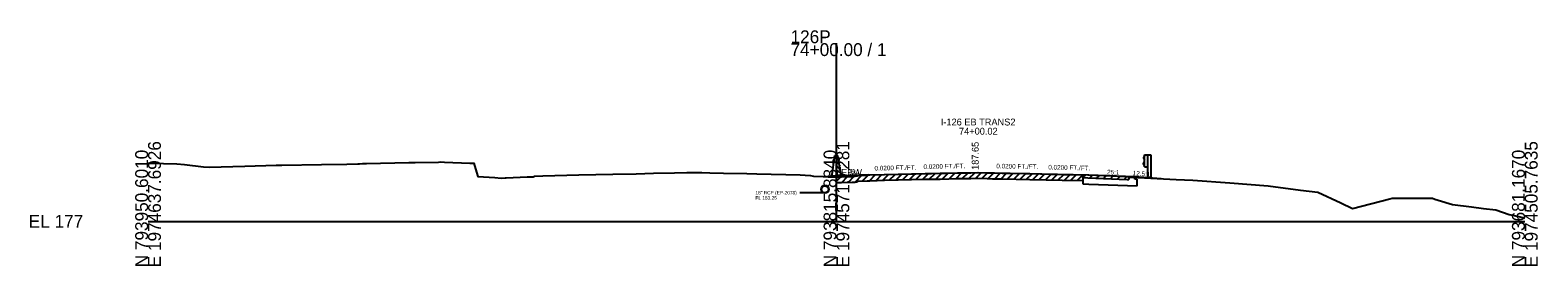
# Model space of a CAD drawing. Extents: x -161 to 1970889, y -4362 to 797231.
# Drawn here: x 2974.3 to 3302.8, y 5490.3 to 5541.7 of the extents above; entities that cross this region are included whole.
import ezdxf

# ---------------------------------------------------------------- set-up
doc = ezdxf.new("R2010")
doc.units = 0
for name, color, linetype in [('RD_GPK_XS_Cell', 7, 'Continuous'), ('RD_XS_Base', 7, 'Continuous'), ('RD_XS_EarthShd', 7, 'Continuous'), ('RD_XS_ExGround', 7, 'Continuous'), ('RD_XS_ExPaveRet', 7, 'Continuous'), ('RD_XS_GR', 7, 'Continuous'), ('RD_XS_MedBWall', 7, 'Continuous'), ('RD_XS_Misc_Line', 7, 'Continuous'), ('RD_XS_Pave', 7, 'Continuous'), ('RD_XS_PaveOvlay', 7, 'Continuous'), ('RD_XS_PaveShd', 7, 'Continuous'), ('RD_XS_Pipe', 7, 'Continuous'), ('RD_XS_TieSlope', 7, 'Continuous'), ('RD_XS_TX_Elev_EX', 7, 'Continuous'), ('RD_XS_TX_Elev_PR', 7, 'Continuous'), ('RD_XS_TX_MkPT', 7, 'Continuous'), ('RD_XS_TX_Profile', 7, 'Continuous'), ('RD_XS_TX_ShdSlope', 7, 'Continuous'), ('RD_XS_TX_Slope', 7, 'Continuous'), ('RD_XS_TX_Station', 7, 'Continuous')]:
    doc.layers.add(name, color=color, linetype=linetype)

msp = doc.modelspace()

# ---------------------------------------------------------------- linework, layer by layer
at = {"layer": 'RD_GPK_XS_Cell'}
for p, q in [((3150, 5500), (3150, 5538.83)), ((3000, 5500), (3150, 5500)), ((3150, 5500), (3300, 5500))]:
    msp.add_line(p, q, dxfattribs=at)
at = {"layer": 'RD_XS_Base'}
for p, q in [((3215, 5509.21), (3215, 5509.77)), ((3203.7, 5508.16), (3205, 5508.13)), ((3205, 5508.13), (3215.5, 5507.71)), ((3215.5, 5509.19), (3215, 5509.21)), ((3215.5, 5507.71), (3215.5, 5509.19))]:
    msp.add_line(p, q, dxfattribs=at)
at = {"layer": 'RD_XS_EarthShd'}
msp.add_line((3215, 5509.77), (3217, 5509.61), dxfattribs=at)
at = {"layer": 'RD_XS_ExGround'}
msp.add_lwpolyline([(3000, 5512.7), (3000.47, 5512.69), (3006.29, 5512.51), (3007.93, 5512.43), (3012.07, 5511.92), (3013.35, 5511.81), (3021.06, 5512.04), (3027.92, 5512.24), (3029.16, 5512.26), (3037.79, 5512.41), (3043.29, 5512.5), (3045.71, 5512.53), (3046.05, 5512.55), (3046.71, 5512.58), (3047.29, 5512.59), (3047.6, 5512.58), (3056.8, 5512.82), (3058.23, 5512.84), (3063.31, 5512.93), (3063.77, 5512.94), (3064.62, 5512.91), (3070.11, 5512.72), (3070.54, 5512.72), (3070.97, 5512.72), (3071.54, 5510.75), (3071.86, 5509.79), (3075.53, 5509.54), (3076.94, 5509.44), (3077.78, 5509.46), (3078.02, 5509.52), (3082.64, 5509.7), (3083.9, 5509.74), (3084.23, 5509.86), (3085.99, 5509.91), (3093.85, 5510.13), (3101.28, 5510.28), (3106.34, 5510.38), (3110.11, 5510.47), (3114.69, 5510.59), (3117.42, 5510.65), (3118.24, 5510.67), (3120.65, 5510.62), (3122.42, 5510.59), (3125.41, 5510.54), (3130.46, 5510.45), (3132.67, 5510.39), (3142.08, 5510.12), (3143.18, 5510.06), (3144.34, 5510.01), (3145.03, 5509.87), (3147.09, 5509.77), (3148.17, 5509.72), (3150, 5509.74), (3150.41, 5509.74), (3151.07, 5509.74), (3153.45, 5509.81), (3154.06, 5509.83), (3154.5, 5509.89), (3154.76, 5510.01), (3156.68, 5510.09), (3157.25, 5510.12), (3160.46, 5510.2), (3169.33, 5510.42), (3172.63, 5510.48), (3176.4, 5510.56), (3179.28, 5510.6), (3180.83, 5510.63), (3182.84, 5510.58), (3184.03, 5510.55), (3186.11, 5510.51), (3192.13, 5510.4), (3199.21, 5510.25), (3204.8, 5510.13), (3213.32, 5509.76), (3213.7, 5509.75), (3214.1, 5509.65), (3214.99, 5509.61), (3215.74, 5509.57), (3224.02, 5509.16), (3227.63, 5508.98), (3235.7, 5508.41), (3244.09, 5507.72), (3251.15, 5506.8), (3254.93, 5506.34), (3259.89, 5504.03), (3262.47, 5502.81), (3270.6, 5504.91), (3271.1, 5505.04), (3279.43, 5505.04), (3279.88, 5505.04), (3280.41, 5504.87), (3281.14, 5504.65), (3284.22, 5503.71), (3288.39, 5503.16), (3290.99, 5502.81), (3293.69, 5502.52), (3296.6, 5501.51), (3298.73, 5501.05), (3300, 5500.69)], dxfattribs=at)
at = {"layer": 'RD_XS_ExPaveRet'}
for p, q in [((3150, 5508.49), (3150, 5509.74)), ((3203.7, 5509.53), (3203.7, 5510.15)), ((3203.7, 5510.15), (3203.7, 5508.9)), ((3203.7, 5509.53), (3204.8, 5509.5)), ((3204.8, 5509.5), (3213.32, 5509.14)), ((3213.7, 5509.75), (3213.7, 5509.12)), ((3213.32, 5509.14), (3213.7, 5509.12))]:
    msp.add_line(p, q, dxfattribs=at)
msp.add_lwpolyline([(3150, 5508.49), (3150.41, 5508.49), (3151.07, 5508.49), (3153.45, 5508.56), (3154.06, 5508.58), (3154.5, 5508.64), (3154.76, 5508.76), (3156.68, 5508.84), (3157.25, 5508.87), (3160.46, 5508.95), (3169.33, 5509.17), (3172.63, 5509.23), (3176.4, 5509.31), (3179.28, 5509.35), (3180.83, 5509.38), (3182.84, 5509.33), (3184.03, 5509.3), (3186.11, 5509.26), (3192.13, 5509.15), (3199.21, 5509), (3203.7, 5508.9)], dxfattribs=at)
at = {"layer": 'RD_XS_GR'}
for p, q in [((3217.15, 5514.32), (3216.88, 5513.88)), ((3216.88, 5513.88), (3216.88, 5513.77)), ((3216.88, 5513.77), (3217.15, 5513.33)), ((3216.88, 5512.63), (3217.15, 5513.07)), ((3217.15, 5514.48), (3217.81, 5514.48)), ((3217.15, 5511.92), (3217.15, 5514.48)), ((3217.81, 5514.48), (3218.48, 5514.48)), ((3217.81, 5514.48), (3217.81, 5509.54)), ((3218.48, 5514.48), (3218.48, 5509.43)), ((3216.88, 5512.52), (3216.88, 5512.63)), ((3217.15, 5512.08), (3216.88, 5512.52)), ((3217.15, 5511.92), (3217.81, 5511.92))]:
    msp.add_line(p, q, dxfattribs=at)
at = {"layer": 'RD_XS_MedBWall'}
for p, q in [((3148.97, 5509.73), (3149.67, 5514.39)), ((3150, 5514.39), (3149.67, 5514.39)), ((3150, 5514.39), (3150.33, 5514.39)), ((3151, 5509.91), (3150.33, 5514.39))]:
    msp.add_line(p, q, dxfattribs=at)
at = {"layer": 'RD_XS_Misc_Line'}
for p, q in [((3150, 5508.76), (3150.98, 5509.74)), ((3151.14, 5508.49), (3152.43, 5509.78)), ((3152.6, 5508.53), (3153.89, 5509.83)), ((3154.06, 5508.58), (3155.52, 5510.04)), ((3155.69, 5508.8), (3157, 5510.11)), ((3157.17, 5508.87), (3158.46, 5510.15)), ((3158.63, 5508.9), (3159.91, 5510.18)), ((3160.07, 5508.94), (3161.36, 5510.22)), ((3161.52, 5508.97), (3162.81, 5510.25)), ((3162.97, 5509.01), (3164.26, 5510.29)), ((3164.42, 5509.04), (3165.71, 5510.33)), ((3165.88, 5509.08), (3167.16, 5510.36)), ((3167.33, 5509.12), (3168.61, 5510.4)), ((3168.78, 5509.15), (3170.05, 5510.43)), ((3170.22, 5509.18), (3171.49, 5510.46)), ((3171.66, 5509.21), (3172.94, 5510.48)), ((3173.1, 5509.24), (3174.38, 5510.51)), ((3174.55, 5509.27), (3175.82, 5510.54)), ((3175.99, 5509.3), (3177.26, 5510.57)), ((3177.43, 5509.32), (3178.7, 5510.59)), ((3178.86, 5509.34), (3180.14, 5510.61)), ((3180.3, 5509.37), (3181.55, 5510.61)), ((3181.71, 5509.36), (3182.93, 5510.58)), ((3183.09, 5509.32), (3184.31, 5510.55)), ((3184.48, 5509.3), (3185.7, 5510.52)), ((3185.86, 5509.27), (3187.09, 5510.5)), ((3187.25, 5509.24), (3188.48, 5510.47)), ((3188.64, 5509.22), (3189.87, 5510.44)), ((3190.03, 5509.19), (3191.26, 5510.42)), ((3191.42, 5509.17), (3192.64, 5510.39)), ((3192.8, 5509.14), (3194.03, 5510.36)), ((3194.19, 5509.11), (3195.41, 5510.33)), ((3195.57, 5509.08), (3196.8, 5510.3)), ((3196.96, 5509.05), (3198.18, 5510.27)), ((3198.34, 5509.02), (3199.57, 5510.24)), ((3199.73, 5508.99), (3200.95, 5510.21)), ((3201.11, 5508.96), (3202.33, 5510.18)), ((3202.49, 5508.93), (3203.7, 5510.14)), ((3203.7, 5509.53), (3204.32, 5510.14)), ((3205.2, 5509.49), (3205.8, 5510.09)), ((3206.7, 5509.42), (3207.3, 5510.02)), ((3208.2, 5509.36), (3208.8, 5509.96)), ((3209.7, 5509.29), (3210.3, 5509.89)), ((3211.2, 5509.23), (3211.8, 5509.83)), ((3212.7, 5509.16), (3213.3, 5509.76))]:
    msp.add_line(p, q, dxfattribs=at)
at = {"layer": 'RD_XS_Pave'}
for p, q in [((3157, 5510.17), (3181, 5510.65)), ((3181, 5510.65), (3205, 5510.17))]:
    msp.add_line(p, q, dxfattribs=at)
at = {"layer": 'RD_XS_PaveOvlay'}
msp.add_line((3203.7, 5510.15), (3203.7, 5508.16), dxfattribs=at)
msp.add_lwpolyline([(3150, 5509.74), (3150.41, 5509.74), (3151.07, 5509.74), (3153.45, 5509.81), (3154.06, 5509.83), (3154.5, 5509.89), (3154.76, 5510.01), (3156.68, 5510.09), (3157.25, 5510.12), (3160.46, 5510.2), (3169.33, 5510.42), (3172.63, 5510.48), (3176.4, 5510.56), (3179.28, 5510.6), (3180.83, 5510.63), (3182.84, 5510.58), (3184.03, 5510.55), (3186.11, 5510.51), (3192.13, 5510.4), (3199.21, 5510.25), (3203.7, 5510.15)], dxfattribs=at)
at = {"layer": 'RD_XS_PaveShd'}
for p, q in [((3157, 5510.17), (3148.99, 5509.85)), ((3205, 5510.17), (3215, 5509.77))]:
    msp.add_line(p, q, dxfattribs=at)
at = {"layer": 'RD_XS_Pipe'}
msp.add_line((3147, 5506.25), (3142, 5506.25), dxfattribs=at)
for radius in [0.85, 0.75]:
    msp.add_circle((3147.5, 5507), radius, dxfattribs=at)
at = {"layer": 'RD_XS_TieSlope'}
for p in [(3217, 5509.61), (3220.75, 5509.32)]:
    msp.add_line(p, (3220.75, 5509.32), dxfattribs=at)

# ---------------------------------------------------------------- texts
at = {"layer": 'RD_GPK_XS_Cell'}
for s, p in [('126P', (3140, 5538.83)), ('74+00.00 / 1', (3140, 5536.03)), ('EL 177', (2974, 5498.6))]:
    msp.add_text(s, height=2.8, dxfattribs=at).set_placement(p)
for s, p in [('E 1974637.6926', (3002.8, 5490)), ('E 1974571.7281', (3152.8, 5490)), ('E 1974505.7635', (3302.8, 5490)), ('N 793950.6010', (3000, 5490)), ('N 793815.8840', (3150, 5490)), ('N 793681.1670', (3300, 5490))]:
    msp.add_text(s, height=2.8, rotation=90, dxfattribs=at).set_placement(p)
at = {"layer": 'RD_XS_ExGround'}
msp.add_text('186.74', height=1, rotation=90, dxfattribs=at).set_placement((3150.96, 5509.75))
at = {"layer": 'RD_XS_Pipe'}
for s, p in [('18" RCP (EP-2078)', (3132.35, 5505.88)), ('FL 183.25', (3132.35, 5504.75))]:
    msp.add_text(s, height=0.75, dxfattribs=at).set_placement(p)
at = {"layer": 'RD_XS_TX_Elev_EX'}
msp.add_text('186.74', height=1, rotation=90, dxfattribs=at).set_placement((3151, 5509.74))
at = {"layer": 'RD_XS_TX_Elev_PR'}
msp.add_text(' 187.65', height=1.5, rotation=90, dxfattribs=at).set_placement((3181, 5510.65))
at = {"layer": 'RD_XS_TX_MkPT'}
msp.add_text('EBW', height=1.5, dxfattribs=at).set_placement((3151, 5509.91))
at = {"layer": 'RD_XS_TX_Profile'}
for rotation, p in [(2.2906, (3152.44, 5510.24)), (357.7094, (3208.96, 5510.26))]:
    msp.add_text('25:1', height=1, rotation=rotation, dxfattribs=at).set_placement(p)
at = {"layer": 'RD_XS_TX_ShdSlope'}
msp.add_text('12.5:1', height=1, rotation=355.4261, dxfattribs=at).set_placement((3214.54, 5510.06))
at = {"layer": 'RD_XS_TX_Slope'}
for rotation, p in [(1.1458, (3158.3, 5511.08)), (1.1458, (3168.98, 5511.41)), (358.8542, (3184.83, 5511.57)), (358.5681, (3196.15, 5511.32))]:
    msp.add_text('0.0200 FT./FT.', height=1, rotation=rotation, dxfattribs=at).set_placement(p)
at = {"layer": 'RD_XS_TX_Station'}
for s, p in [('I-126 EB TRANS2', (3172.74, 5520.9)), ('74+00.02', (3176.71, 5518.9))]:
    msp.add_text(s, height=1.5, dxfattribs=at).set_placement(p)

doc.saveas('drawing.dxf')
